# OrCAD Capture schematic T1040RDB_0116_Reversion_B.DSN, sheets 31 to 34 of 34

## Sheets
31 31 Pwr Switch: size B
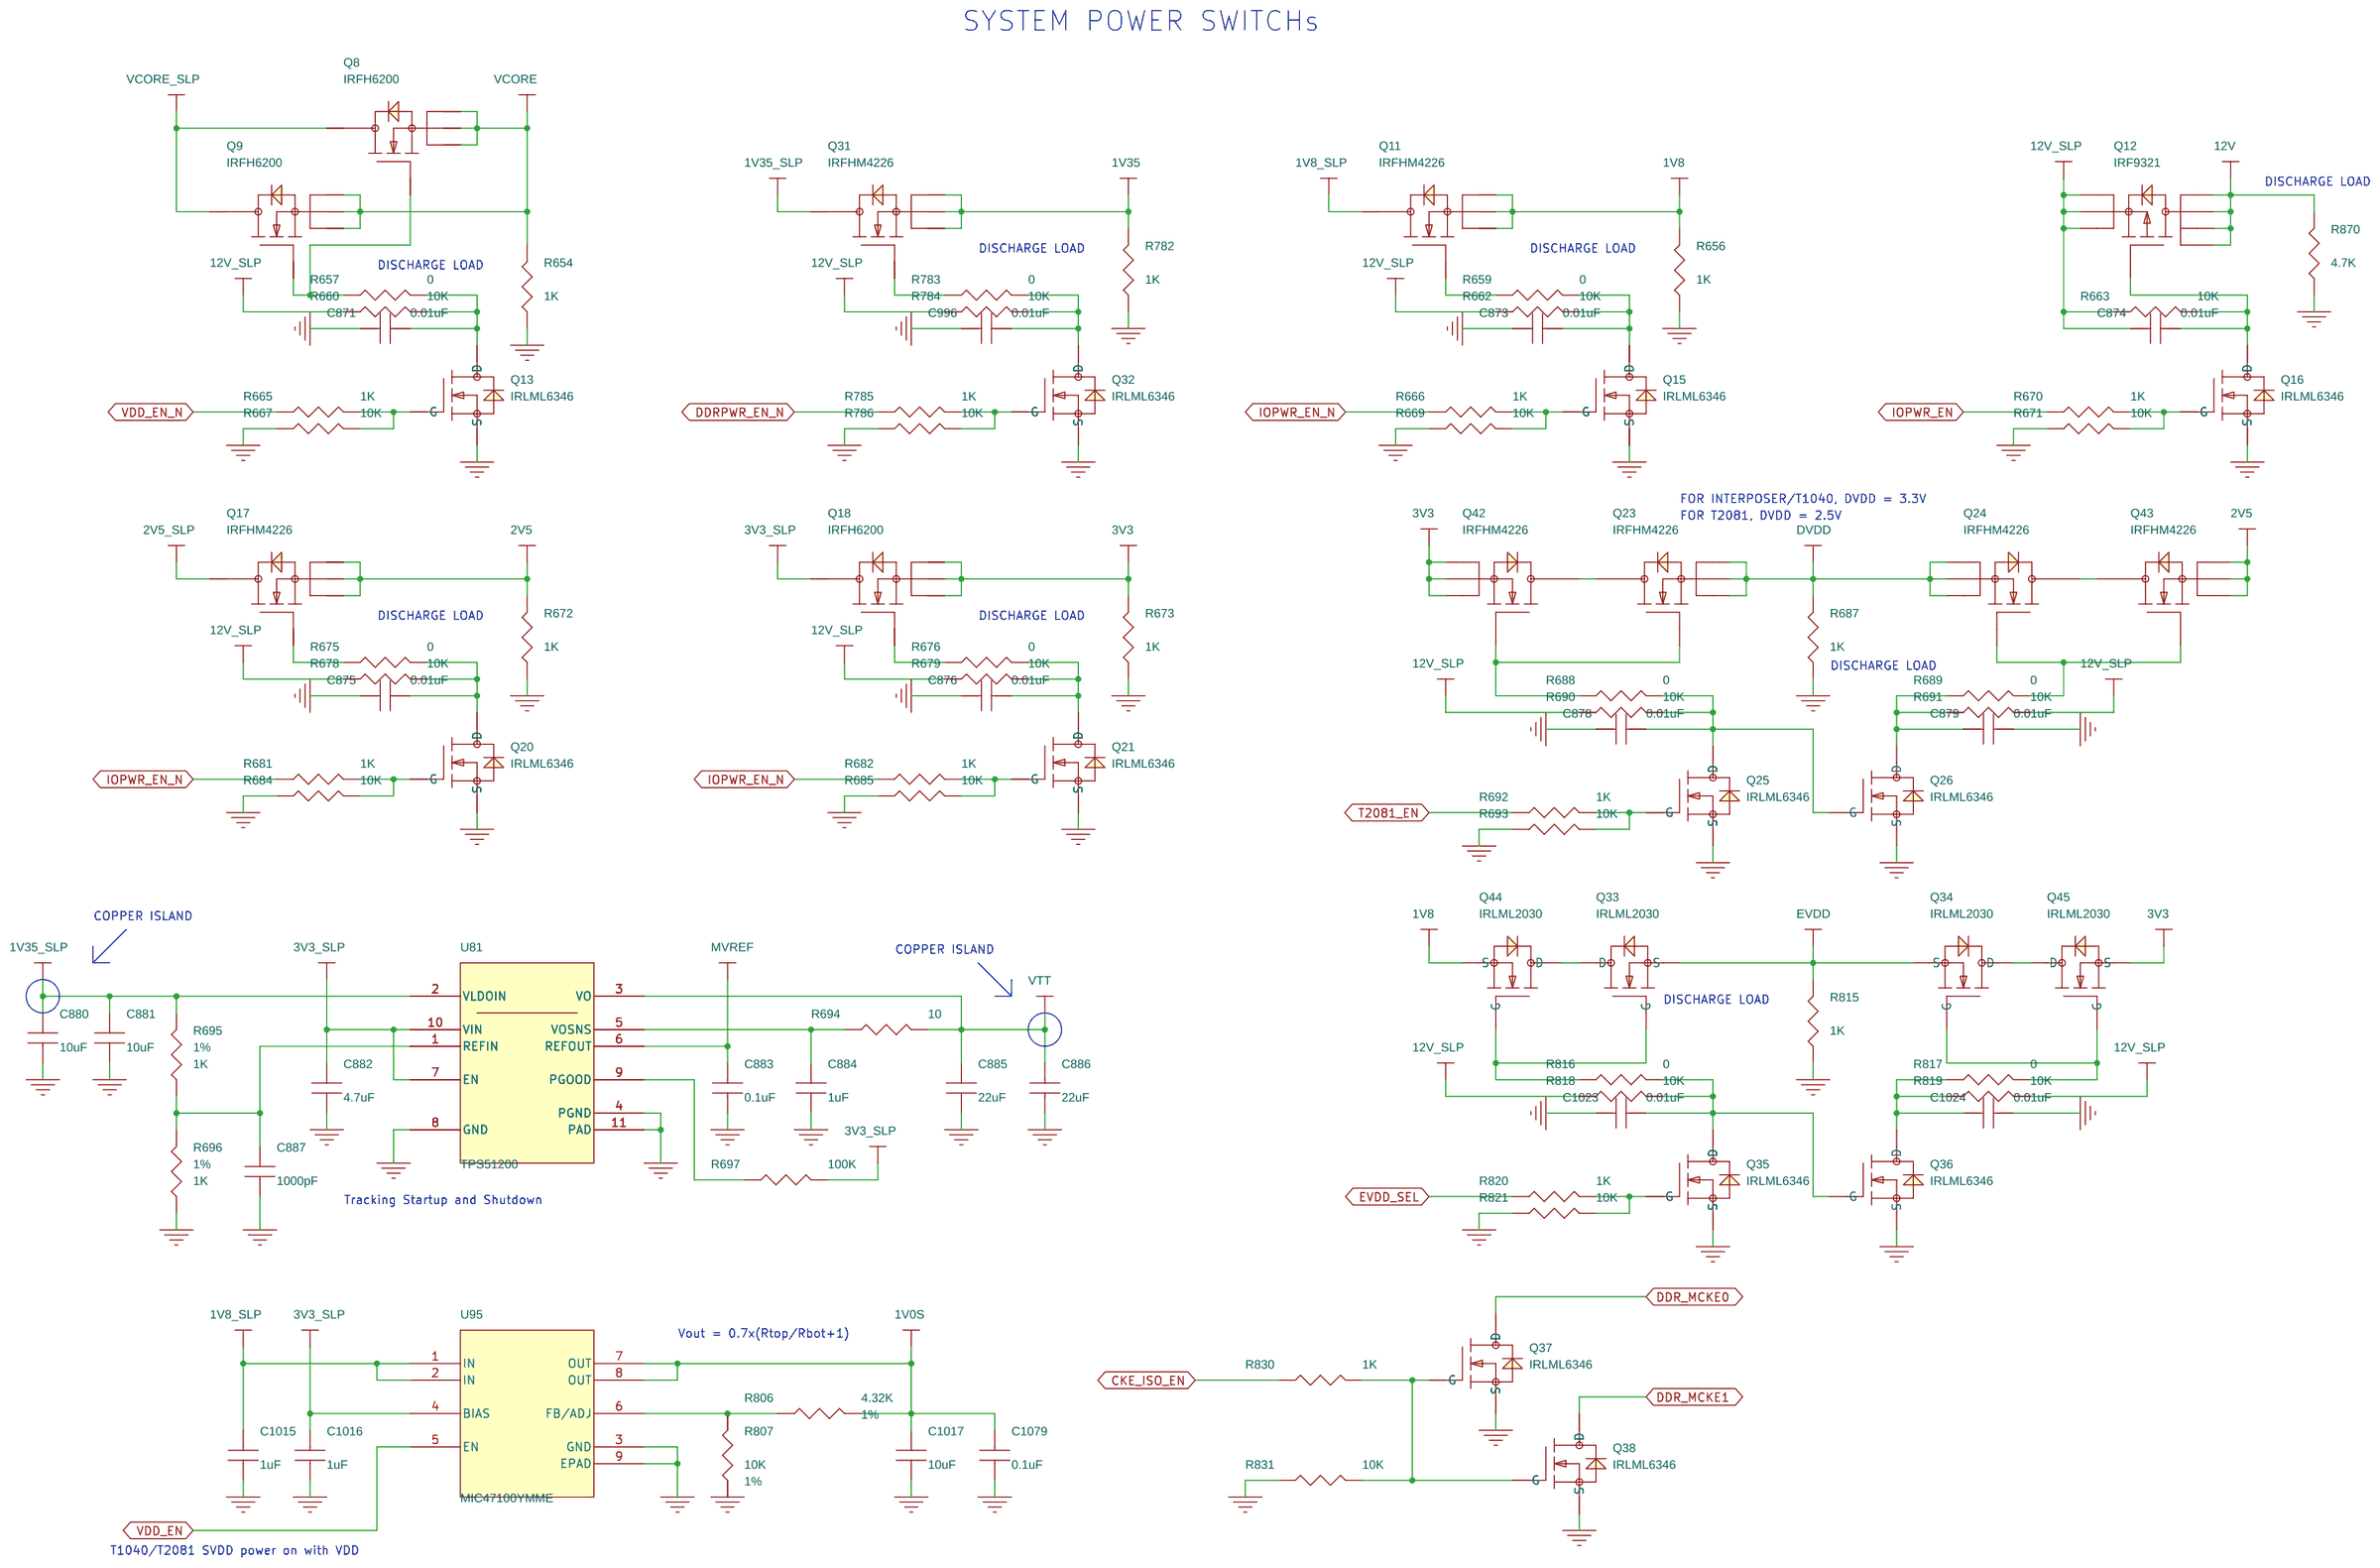
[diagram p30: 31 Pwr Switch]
32 32 Pwr In: size B
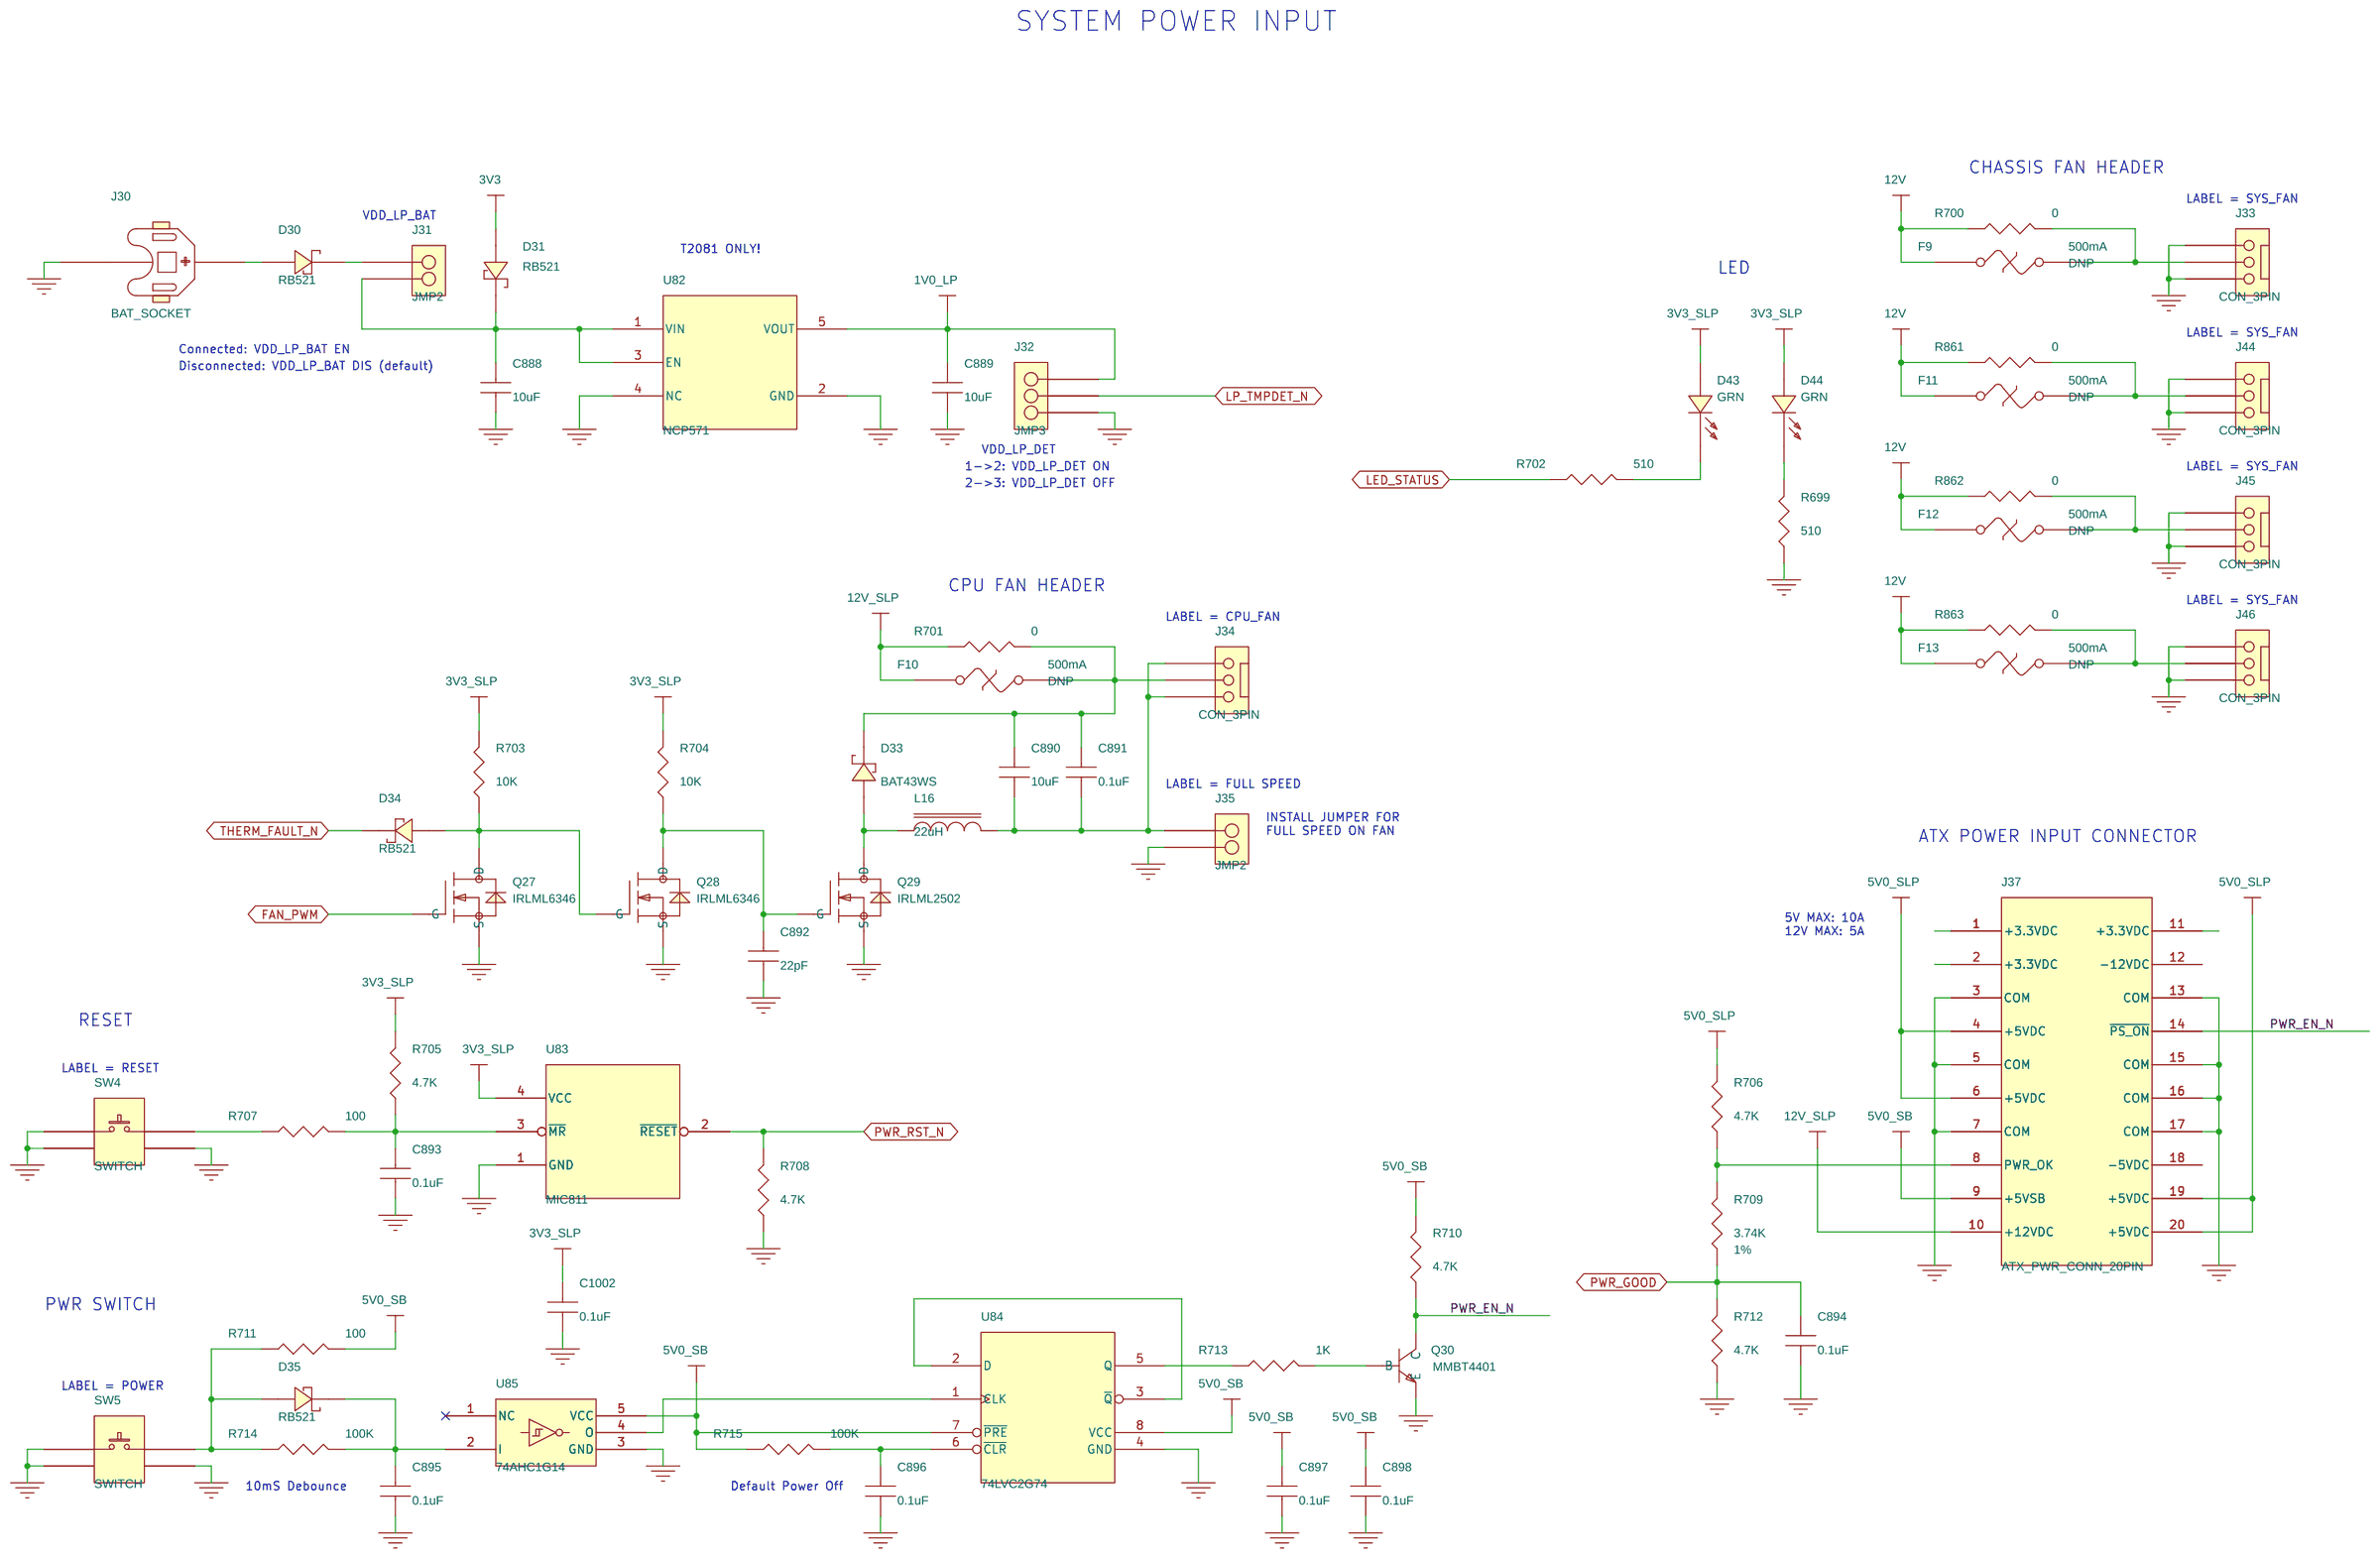
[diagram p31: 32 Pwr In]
33 33 MEC: size B
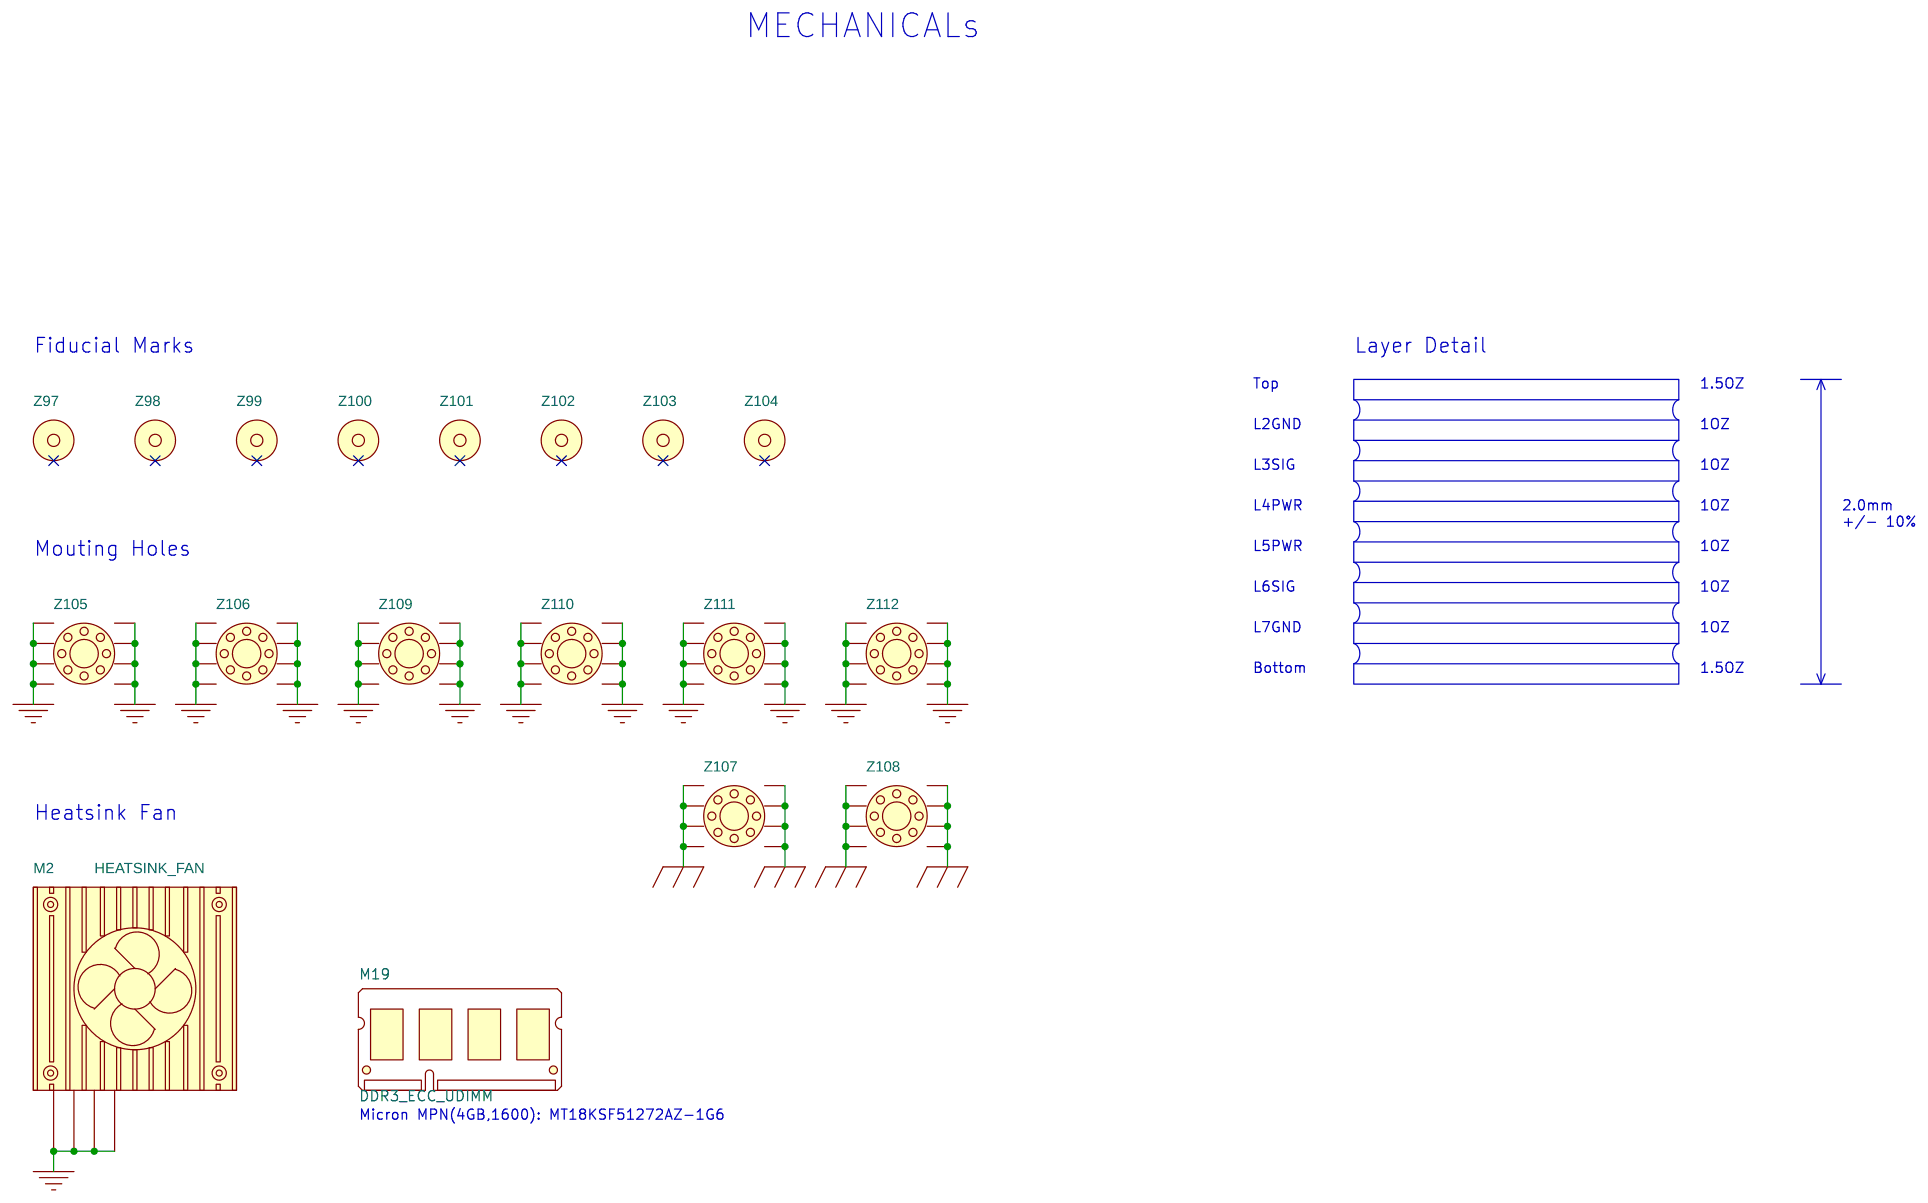
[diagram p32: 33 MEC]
34 34 Change List
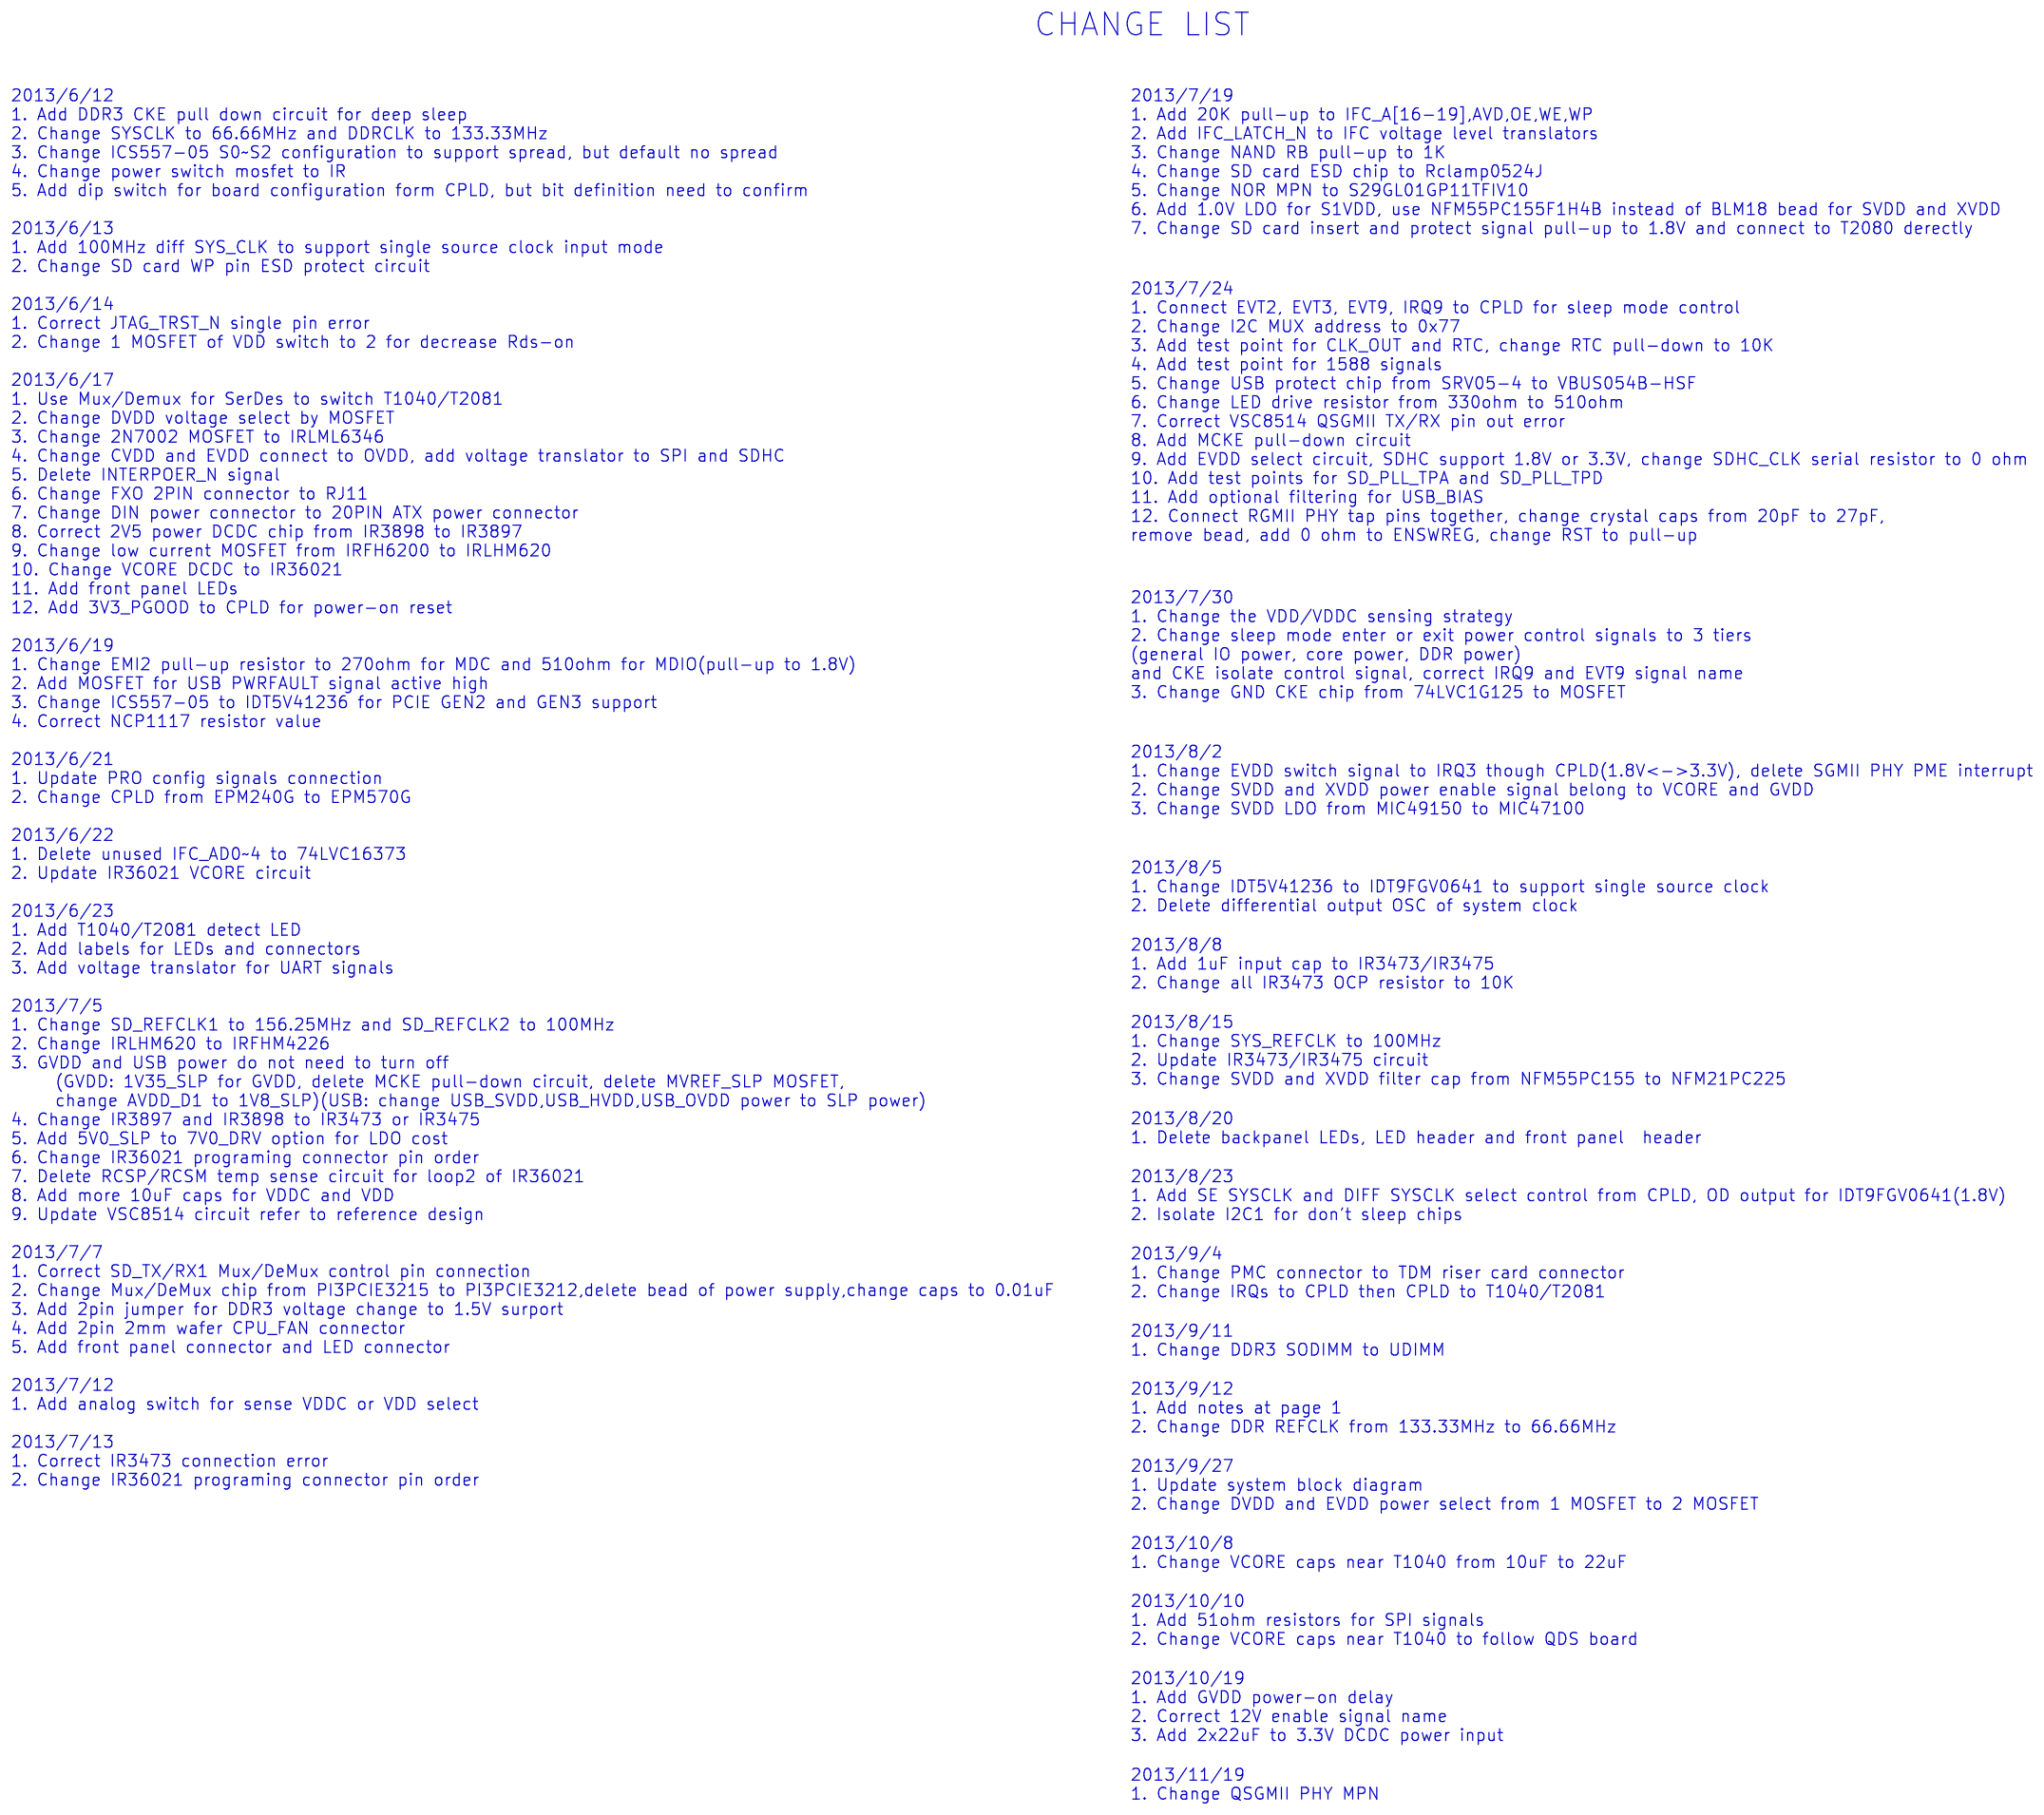
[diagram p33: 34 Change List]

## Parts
sheet 31 Pwr Switch
C871  0.01uF  [0402]
C873  0.01uF  [0402]
C874  0.01uF  [0402]
C875  0.01uF  [0402]
C876  0.01uF  [0402]
C878  0.01uF  [0402]
C879  0.01uF  [0402]
C880  10uF  [0603]
C881  10uF  [0603]
C882  4.7uF  [0603]
C883  0.1uF  [0402]
C884  1uF  [0402]
C885  22uF  [0805]
C886  22uF  [0805]
C887  1000pF  [0402]
C996  0.01uF  [0402]
C1015  1uF  [0402]
C1016  1uF  [0402]
C1017  10uF  [0603]
C1023  0.01uF  [0402]
C1024  0.01uF  [0402]
C1079  0.1uF  [0402]
Q8  IRFH6200  [so_8_fl]
Q9  IRFH6200  [so_8_fl]
Q11  IRFHM4226  [u8_fl]
Q12  IRF9321  [so_8]
Q13  IRLML6346  [sot23]
Q15  IRLML6346  [sot23]
Q16  IRLML6346  [sot23]
Q17  IRFHM4226  [u8_fl]
Q18  IRFH6200  [so_8_fl]
Q20  IRLML6346  [sot23]
Q21  IRLML6346  [sot23]
Q23  IRFHM4226  [u8_fl]
Q24  IRFHM4226  [u8_fl]
Q25  IRLML6346  [sot23]
Q26  IRLML6346  [sot23]
Q31  IRFHM4226  [u8_fl]
Q32  IRLML6346  [sot23]
Q33  IRLML2030  [sot23]
Q34  IRLML2030  [sot23]
Q35  IRLML6346  [sot23]
Q36  IRLML6346  [sot23]
Q37  IRLML6346  [sot23]
Q38  IRLML6346  [sot23]
Q42  IRFHM4226  [u8_fl]
Q43  IRFHM4226  [u8_fl]
Q44  IRLML2030  [sot23]
Q45  IRLML2030  [sot23]
R654  1K  [0402]
R656  1K  [0402]
R657  0  [0402]
R659  0  [0402]
R660  10K  [0402]
R662  10K  [0402]
R663  10K  [0402]
R665  1K  [0402]
R666  1K  [0402]
R667  10K  [0402]
R669  10K  [0402]
R670  1K  [0402]
R671  10K  [0402]
R672  1K  [0402]
R673  1K  [0402]
R675  0  [0402]
R676  0  [0402]
R678  10K  [0402]
R679  10K  [0402]
R681  1K  [0402]
R682  1K  [0402]
R684  10K  [0402]
R685  10K  [0402]
R687  1K  [0402]
R688  0  [0402]
R689  0  [0402]
R690  10K  [0402]
R691  10K  [0402]
R692  1K  [0402]
R693  10K  [0402]
R694  10  [0402]
R695  1K  [0402]
R696  1K  [0402]
R697  100K  [0402]
R782  1K  [0402]
R783  0  [0402]
R784  10K  [0402]
R785  1K  [0402]
R786  10K  [0402]
R806  4.32K  [0402]
R807  10K  [0402]
R815  1K  [0402]
R816  0  [0402]
R817  0  [0402]
R818  10K  [0402]
R819  10K  [0402]
R820  1K  [0402]
R821  10K  [0402]
R830  1K  [0402]
R831  10K  [0402]
R870  4.7K  [0402]
U81  TPS51200  [dfn_p050_d040_b300_10_e240x165]
U95  MIC47100YMME  [msop_8_e170]
sheet 32 Pwr In
C888  10uF  [0603]
C889  10uF  [0603]
C890  10uF  [1206]
C891  0.1uF  [0603]
C892  22pF  [0402]
C893  0.1uF  [0402]
C894  0.1uF  [0402]
C895  0.1uF  [0402]
C896  0.1uF  [0402]
C897  0.1uF  [0402]
C898  0.1uF  [0402]
C1002  0.1uF  [0402]
D30  RB521  [sod523]
D31  RB521  [sod523]
D33  BAT43WS  [sod323]
D34  RB521  [sod523]
D35  RB521  [sod523]
D43  GRN  [led_pm_1s]
D44  GRN  [led_pm_1s]
F9  500mA  [1206]
F10  500mA  [1206]
F11  500mA  [1206]
F12  500mA  [1206]
F13  500mA  [1206]
J30  BAT_SOCKET  [con_bat_wba3b2]
J31  JMP2  [jmp_p254_t_1x2]
J32  JMP3  [hdr_p254_m_t_1x3]
J33  CON_3PIN  [con_wafer_p254_s_1x3]
J34  CON_3PIN  [con_wafer_p254_s_1x3]
J35  JMP2  [jmp_p254_t_1x2]
J37  ATX_PWR_CONN_20PIN  [con_atx_20pin]
J44  CON_3PIN  [con_wafer_p254_s_1x3]
J45  CON_3PIN  [con_wafer_p254_s_1x3]
J46  CON_3PIN  [con_wafer_p254_s_1x3]
L16  22uH  [ind_45x40]
Q27  IRLML6346  [sot23]
Q28  IRLML6346  [sot23]
Q29  IRLML2502  [sot23]
Q30  MMBT4401  [sot23]
R699  510  [0402]
R700  0  [1206]
R701  0  [1206]
R702  510  [0402]
R703  10K  [0402]
R704  10K  [0402]
R705  4.7K  [0402]
R706  4.7K  [0402]
R707  100  [0402]
R708  4.7K  [0402]
R709  3.74K  [0402]
R710  4.7K  [0402]
R711  100  [0402]
R712  4.7K  [0402]
R713  1K  [0402]
R714  100K  [0402]
R715  100K  [0402]
R861  0  [1206]
R862  0  [1206]
R863  0  [1206]
SW4  SWITCH  [con_sw_60x60_2p2_34]
SW5  SWITCH  [con_sw_60x60_2p2_34]
U82  NCP571  [sot23_5]
U83  MIC811  [sot143]
U84  74LVC2G74  [u8]
U85  74AHC1G14  [sc70_5]
sheet 33 MEC
M2  HEATSINK_FAN  [hs_t1040]
M19  DDR3_ECC_UDIMM  [none]
Z97  FIDUCIAL  [fiducial]
Z98  FIDUCIAL  [fiducial]
Z99  FIDUCIAL  [fiducial]
Z100  FIDUCIAL  [fiducial]
Z101  FIDUCIAL  [fiducial]
Z102  FIDUCIAL  [fiducial]
Z103  FIDUCIAL  [fiducial]
Z104  FIDUCIAL  [fiducial]
Z105  MH_M8  [mh_900c400n_m]
Z106  MH_M8  [mh_900c400n_m]
Z107  MH_M8  [mh_900c400n_m]
Z108  MH_M8  [mh_900c400n_m]
Z109  MH_M8  [mh_900c400n_m]
Z110  MH_M8  [mh_900c400n_m]
Z111  MH_M8  [mh_900c400n_m]
Z112  MH_M8  [mh_900c400n_m]

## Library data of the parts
C871 C873-C876 C878 C879 C890 C891 C996 C1023 C1024 = CAP: VOLTAGE: 25V
C880-C882 C884-C886 C888 C889 C1015-C1017 = CAP: VOLTAGE: 6.3V
C883 C893-C898 C1002 C1079 = CAP: VOLTAGE: 16V
C887 C892 = CAP: VOLTAGE: 50V
Q8 Q9 Q18 = NMOS_SO8FL: MPN: IRFH6200TRPBF; TYPE: MOS; Vendor: IR
Q11 Q17 Q23 Q24 Q31 Q42 Q43 = NMOS_SO8FL: MPN: IRFHM4226TRPBF; TYPE: MOS; Vendor: IR
Q12 = PMOS_SO8: MPN: IRF9321TRPBF; TYPE: MOS; Vendor: IR
Q13 Q15 Q16 Q20 Q21 Q25-Q28 Q32 Q35-Q38 = NMOS: MPN: IRLML6346TRPBF; TYPE: MOS; Vendor: IR
Q33 Q34 Q44 Q45 = NMOS: MPN: IRLML2030TRPBF; TYPE: MOS; Vendor: IR
R654 R656 R657 R659 R660 R662 R663 R665-R667 R669-R673 R675 R676 R678 R679 R681 R682 R684 R685 R687-R694 R697 R699-R708 R710-R715 R782-R786 R815-R821 R830 R831 R861-R863 R870 = RES: TOL: 5%
R695 R696 R709 R806 R807 = RES: TOL: 1%
U81 = TPS51200: MPN: TPS51200DRCT; TYPE: IC; Vendor: TI
U95 = MIC47100-MSOP8: MPN: MIC49150YMM; TYPE: IC; Vendor: Micrel
D30 D31 D34 D35 = DIODE_SCHOTTKY: MPN: RB521S30T1G; TYPE: DIODE; Vendor: ON Semi
D33 = DIODE_SCHOTTKY: MPN: BAT43WS-7-F; TYPE: DIODE; Vendor: DIODES
D43 D44 = LED: MPN: L-96A8YVP/1GD/TG-0L; Vendor: Kingbrignt
F9-F13 = PTC: BOM_IGNORE: DNP; MPN: 1206L050; Vendor: Littelfuse
J30 = BAT_SOCKET: MPN: WBA3B2 U; TYPE: CON; Vendor: WIN WIN PRECISION INDUSTRIAL
J31 J35 = CONN_1X2: MPN: TSW-102-07-F-S; TYPE: HDR; Vendor: Samtec
J32 = CONN_1X3: MPN: TSW-103-07-F-S; TYPE: HDR; Vendor: Samtec
J33 J34 J44-J46 = CONN_3PIN: MPN: WRFB-DS03T2NNAX-X; TYPE: HDR; Vendor: SUPERIOR TECH
J37 = ATX_PWR_CONN_20PIN: MPN: 5566-20A; TYPE: CON; Vendor: MOLEX
L16 = IND_IRON: MPN: MDR43SG220M; TYPE: IND; Vendor: MNC
Q29 = NMOS: MPN: IRLML2502TRPBF; TYPE: MOS; Vendor: IR
Q30 = TRANS_NPN: MPN: MMBT4401T-7-F; TYPE: TRAN; Vendor: DIODES
SW4 SW5 = SWITCH_2P2: MPN: KFC-01-01-01-6*6*7; TYPE: CON; Vendor: UNIT
U82 = NCP571: MPN: NCP571SN10T1G; TYPE: IC; Vendor: ON Semi
U83 = MAX811S: MPN: MIC811SUY; TYPE: IC; Vendor: Micrel
U84 = 74LVC2G74: MPN: SN74LVC2G74DCUR; TYPE: IC; Vendor: TI
U85 = 74LVC1G14: MPN: SN74AHC1G14DCKR; TYPE: IC; Vendor: TI
M2 = HEATSINK_FAN: TYPE: MEC
M19 = DDR_MDL: MPN: MT18KSF51272AZ-1G6; TYPE: MDL; Vendor: Micron
Z97-Z104 = FIDUCIAL
Z105-Z112 = MH_M8

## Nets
1V0_LP: C889.1 J32.1 U82.5(VOUT) ; also on sheet 12
1V0S: C1017.1 C1079.1 R806.2 U95.7(OUT) U95.8(OUT) ; also on sheet 12
1V8: Q11.1 Q11.2 Q11.3 Q44.2(S) R656.2 ; also on sheet 8 12 21
1V8_SLP: C1015.1 Q11.5 U95.1(IN) U95.2(IN) ; also on sheet 12 26 27 30
1V35: Q31.1 Q31.2 Q31.3 R782.2 ; also on sheet 12 13
1V35_SLP: C880.1 C881.1 Q31.5 R695.2 U81.2(VLDOIN) ; also on sheet 3 12 30
2V5: Q17.1 Q17.2 Q17.3 Q43.1 Q43.2 Q43.3 R672.2 ; also on sheet 8 12 16 17 18 19 20
2V5_SLP: Q17.5 ; also on sheet 7 8 12 15 30
3V3: D31.2 Q18.1 Q18.2 Q18.3 Q42.1 Q42.2 Q42.3 Q45.2(S) R673.2 ; also on sheet 3 5 6 7 9 10 12 14 16 17 21 22 23 24 28 29
3V3_SLP: C882.1 C1002.1 C1016.1 D43.2 D44.2 Q18.5 R697.2 R703.2 R704.2 R705.2 U81.7(EN) U81.10(VIN) U83.4(VCC) U95.4(BIAS) ; also on sheet 7 11 12 13 15 26 29 30
5V0_SB: C897.1 C898.1 J37.9(+5VSB) R710.2 R711.2 R715.1 U84.7(~{PRE}) U84.8(VCC) U85.5(VCC)
5V0_SLP: J37.4(+5VDC) J37.6(+5VDC) J37.19(+5VDC) J37.20(+5VDC) R706.2 ; also on sheet 11 29 30
12V: F9.1 F11.1 F12.1 F13.1 Q12.5 Q12.6 Q12.7 Q12.8 R700.1 R861.1 R862.1 R863.1 R870.2 ; also on sheet 10 22 25
12V_SLP: C874.1 F10.1 J37.10(+12VDC) Q12.1 Q12.2 Q12.3 R660.1 R662.1 R663.1 R678.1 R679.1 R690.1 R691.2 R701.1 R784.1 R818.1 R819.2 ; also on sheet 29
-5VDC: J37.18(-5VDC)
-12VDC: J37.12(-12VDC)
DVDD: Q23.1 Q23.2 Q23.3 Q24.1 Q24.2 Q24.3 R687.2 ; also on sheet 7 12 14
GND: C871.1 C873.1 C875.1 C876.1 C878.1 C879.2 C880.2 C881.2 C882.2 C883.2 C884.2 C885.2 C886.2 C887.2 C888.2 C889.2 C892.2 C893.2 C894.2 C895.2 C896.2 C897.2 C898.2 C996.1 C1002.2 C1015.2 C1016.2 C1017.2 C1023.1 C1024.2 C1079.2 J30.2 J32.3 J33.1 J33.3 J35.2 J37.3(COM) J37.5(COM) J37.7(COM) J37.13(COM) J37.15(COM) J37.16(COM) J37.17(COM) J44.1 J44.3 J45.1 J45.3 J46.1 J46.3 M2.1 M2.2 M2.3 M2.4 Q13.2(S) Q15.2(S) Q16.2(S) Q20.2(S) Q21.2(S) Q25.2(S) Q26.2(S) Q27.2(S) Q28.2(S) Q29.2(S) Q30.2(E) Q32.2(S) Q35.2(S) Q36.2(S) Q37.2(S) Q38.2(S) R654.1 R656.1 R667.1 R669.1 R671.1 R672.1 R673.1 R684.1 R685.1 R687.1 R693.1 R696.1 R699.1 R708.1 R712.1 R782.1 R786.1 R807.1 R815.1 R821.1 R831.1 R870.1 SW4.1 SW4.3 SW4.4 SW5.1 SW5.3 SW5.4 U81.4(PGND) U81.8(GND) U81.11(PAD) U82.2(GND) U82.4(NC) U83.1(GND) U84.4(GND) U85.3(GND) U95.3(GND) U95.9(EPAD) Z105.1 Z105.2 Z105.3 Z105.4 Z105.5 Z105.6 Z105.7 Z105.8 Z106.1 Z106.2 Z106.3 Z106.4 Z106.5 Z106.6 Z106.7 Z106.8 Z109.1 Z109.2 Z109.3 Z109.4 Z109.5 Z109.6 Z109.7 Z109.8 Z110.1 Z110.2 Z110.3 Z110.4 Z110.5 Z110.6 Z110.7 Z110.8 Z111.1 Z111.2 Z111.3 Z111.4 Z111.5 Z111.6 Z111.7 Z111.8 Z112.1 Z112.2 Z112.3 Z112.4 Z112.5 Z112.6 Z112.7 Z112.8 ; also on sheet 3 4 5 6 7 8 9 10 11 12 13 14 15 16 17 18 19 20 21 22 23 24 25 26 27 28 29 30
VDD_EN: U95.5(EN) ; also on sheet 26
VDD_EN_N: R665.1 ; also on sheet 26
CKE_ISO_EN: R830.1 ; also on sheet 26
DDR_MCKE0: Q37.3(D) ; also on sheet 3
DDR_MCKE1: Q38.3(D) ; also on sheet 3
DDRPWR_EN_N: R785.1 ; also on sheet 26
EARTH: Z107.1 Z107.2 Z107.3 Z107.4 Z107.5 Z107.6 Z107.7 Z107.8 Z108.1 Z108.2 Z108.3 Z108.4 Z108.5 Z108.6 Z108.7 Z108.8 ; also on sheet 11 14 15 16 17 20 21
EVDD: Q33.2(S) Q34.2(S) R815.2 ; also on sheet 6 12
EVDD_SEL: R820.1 ; also on sheet 26
FAN_PWM: Q27.1(G) ; also on sheet 26
IOPWR_EN: R670.1 ; also on sheet 26 30
IOPWR_EN_N: R666.1 R681.1 R682.1 ; also on sheet 26
LED_STATUS: R702.1 ; also on sheet 26
LP_TMPDET_N: J32.2 ; also on sheet 7
MVREF: C883.1 U81.6(REFOUT) ; also on sheet 3
PWR_EN_N: J37.14(~{PS_ON}) Q30.3(C) R710.1
PWR_GOOD: C894.1 R709.1 R712.2 ; also on sheet 26
PWR_RST_N: R708.2 U83.2(~{RESET}) ; also on sheet 26
T2081_EN: R692.1 ; also on sheet 9 26
THERM_FAULT_N: D34.1 ; also on sheet 14 26
VCORE: Q8.1 Q8.2 Q8.3 Q9.1 Q9.2 Q9.3 R654.2 ; also on sheet 12 29
VCORE_SLP: Q8.5 Q9.5 ; also on sheet 12 29
VTT: C885.1 C886.1 R694.2 U81.3(VO) ; also on sheet 3
N17399246: C893.1 R705.1 R707.2 U83.3(~{MR})
N17399288: R707.1 SW4.2
N17400346: D35.2 R711.1 R714.1 SW5.2
N17401317: U84.1(CLK) U85.4(O)
N17401544: C895.1 D35.1 R714.2 U85.2(I)
N17403382: C890.2 C891.2 J34.1 J34.3 J35.1 L16.2
N17403388: C890.1 C891.1 D33.1 F10.2 J34.2 R701.2
N17523688: U84.2(D) U84.3(~{Q})
N17523697: R713.1 U84.5(Q)
N17523706: C896.1 R715.2 U84.6(~{CLR})
N17523733: D33.2 L16.1 Q29.3(D)
N17524661: C892.1 Q28.3(D) Q29.1(G) R704.1
N17525004: D34.2 Q27.3(D) Q28.1(G) R703.1
N18271716: Q15.1(G) R666.2 R669.2
N18271718: C873.2 Q15.3(D) R659.2 R662.2
N18271794: Q11.4 R659.1
N18272048: Q13.1(G) R665.2 R667.2
N18272050: C871.2 Q13.3(D) R657.2 R660.2
N18272126: Q8.4 Q9.4 R657.1
N18272820: C875.2 Q20.3(D) R675.2 R678.2
N18272822: Q20.1(G) R681.2 R684.2
N18272905: Q17.4 R675.1
N18273179: Q21.1(G) R682.2 R685.2
N18273181: C876.2 Q21.3(D) R676.2 R679.2
N18273262: Q18.4 R676.1
N18273767: Q16.1(G) R670.2 R671.2
N18273907: C874.2 Q12.4 Q16.3(D) R663.2
N18275087: C887.1 R695.1 R696.2 U81.1(REFIN)
N18275123: C884.1 R694.1 U81.5(VOSNS)
N18275169: R697.1 U81.9(PGOOD)
N18562864: Q30.1(B) R713.2
N18563122: J37.8(PWR_OK) R706.1 R709.2
N18564716: C878.2 Q25.3(D) Q26.1(G) R688.2 R690.2
N18564718: Q25.1(G) R692.2 R693.2
N18564801: Q23.4 Q42.4 R688.1
N18564847: Q23.5 Q42.5
N18565254: C888.1 D31.1 J31.2 U82.1(VIN) U82.3(EN)
N18565311: D30.1 J31.1
N18565323: D30.2 J30.1
N18566414: C879.1 Q26.3(D) R689.1 R691.1
N18566880: Q24.4 Q43.4 R689.2
N19623883: C996.2 Q32.3(D) R783.2 R784.2
N19623885: Q32.1(G) R785.2 R786.2
N19623968: Q31.4 R783.1
N20366563: R806.1 R807.2 U95.6(FB/ADJ)
N20553507: Q37.1(G) Q38.1(G) R830.2 R831.2
N20559490: Q35.1(G) R820.2 R821.2
N20559492: C1023.2 Q35.3(D) Q36.1(G) R816.2 R818.2
N20559589: Q33.1(G) Q44.1(G) R816.1
N20559634: Q33.3(D) Q44.3(D)
N20559669: C1024.1 Q36.3(D) R817.1 R819.1
N20559724: Q34.1(G) Q45.1(G) R817.2
N22360230: F9.2 J33.2 R700.2
N22360382: F11.2 J44.2 R861.2
N22360534: F12.2 J45.2 R862.2
N22361017: F13.2 J46.2 R863.2
N22361656: D43.1 R702.2
N22361689: D44.1 R699.2
N22440478: Q34.3(D) Q45.3(D)
N22787926: Q24.5 Q43.5

Not connected (* = marked no-connect by the designer): J37 1(+3.3VDC) 2(+3.3VDC) 11(+3.3VDC); U85 1(NC)*; Z97 1*; Z98 1*; Z99 1*; Z100 1*; Z101 1*; Z102 1*; Z103 1*; Z104 1*

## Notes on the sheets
sheet 31
- SYSTEM POWER SWITCHs
- DISCHARGE LOAD
- DISCHARGE LOAD
- DISCHARGE LOAD
- DISCHARGE LOAD
- FOR INTERPOSER/T1040, DVDD = 3.3V
- FOR T2081, DVDD = 2.5V
- DISCHARGE LOAD
- DISCHARGE LOAD
- DISCHARGE LOAD
- COPPER ISLAND
- COPPER ISLAND
- DISCHARGE LOAD
- Tracking Startup and Shutdown
- Vout = 0.7x(Rtop/Rbot+1)
- T1040/T2081 SVDD power on with VDD
sheet 32
- SYSTEM POWER INPUT
- CHASSIS FAN HEADER
- LABEL = SYS_FAN
- VDD_LP_BAT
- T2081 ONLY!
- LED
- LABEL = SYS_FAN
- Connected: VDD_LP_BAT EN
- Disconnected: VDD_LP_BAT DIS (default)
- VDD_LP_DET
- 1->2: VDD_LP_DET ON
- LABEL = SYS_FAN
- 2->3: VDD_LP_DET OFF
- CPU FAN HEADER
- LABEL = SYS_FAN
- LABEL = CPU_FAN
- LABEL = FULL SPEED
- INSTALL JUMPER FOR
  FULL SPEED ON FAN
- ATX POWER INPUT CONNECTOR
- 5V MAX: 10A
  12V MAX: 5A
- RESET
- LABEL = RESET
- PWR SWITCH
- LABEL = POWER
- 10mS Debounce
- Default Power Off
sheet 33
- MECHANICALs
- Fiducial Marks
- Layer Detail
- Top
- 1.5OZ
- L2GND
- 1OZ
- L3SIG
- 1OZ
- L4PWR
- 1OZ
- 2.0mm
  +/- 10%
- Mouting Holes
- L5PWR
- 1OZ
- L6SIG
- 1OZ
- L7GND
- 1OZ
- Bottom
- 1.5OZ
- Heatsink Fan
- Micron MPN(4GB,1600): MT18KSF51272AZ-1G6
sheet 34
- CHANGE LIST
- 2013/6/12
  1. Add DDR3 CKE pull down circuit for deep sleep
  2. Change SYSCLK to 66.66MHz and DDRCLK to 133.33MHz
  3. Change ICS557-05 S0~S2 configuration to support spread, but default no spread
  4. Change power switch mosfet to IR
  5. Add dip switch for board configuration form CPLD, but bit definition need to confirm
  2013/6/13
  1. Add 100MHz diff SYS_CLK to support single source clock input mode
  2. Change SD card WP pin ESD protect circuit
  2013/6/14
  1. Correct JTAG_TRST_N single pin error
  2. Change 1 MOSFET of VDD switch to 2 for decrease Rds-on
  2013/6/17
  1. Use Mux/Demux for SerDes to switch T1040/T2081
  2. Change DVDD voltage select by MOSFET
  3. Change 2N7002 MOSFET to IRLML6346
  4. Change CVDD and EVDD connect to OVDD, add voltage translator to SPI and SDHC
  5. Delete INTERPOER_N signal
  6. Change FXO 2PIN connector to RJ11
  7. Change DIN power connector to 20PIN ATX power connector
  8. Correct 2V5 power DCDC chip from IR3898 to IR3897
  9. Change low current MOSFET from IRFH6200 to IRLHM620
  10. Change VCORE DCDC to IR36021
  11. Add front panel LEDs
  12. Add 3V3_PGOOD to CPLD for power-on reset
  2013/6/19
  1. Change EMI2 pull-up resistor to 270ohm for MDC and 510ohm for MDIO(pull-up to 1.8V)
  2. Add MOSFET for USB PWRFAULT signal active high
  3. Change ICS557-05 to IDT5V41236 for PCIE GEN2 and GEN3 support
  4. Correct NCP1117 resistor value
  2013/6/21
  1. Update PRO config signals connection
  2. Change CPLD from EPM240G to EPM570G
  2013/6/22
  1. Delete unused IFC_AD0~4 to 74LVC16373
  2. Update IR36021 VCORE circuit
  2013/6/23
  1. Add T1040/T2081 detect LED
  2. Add labels for LEDs and connectors
  3. Add voltage translator for UART signals
  2013/7/5
  1. Change SD_REFCLK1 to 156.25MHz and SD_REFCLK2 to 100MHz
  2. Change IRLHM620 to IRFHM4226
  3. GVDD and USB power do not need to turn off
  	(GVDD: 1V35_SLP for GVDD, delete MCKE pull-down circuit, delete MVREF_SLP MOSFET,
  	change AVDD_D1 to 1V8_SLP)(USB: change USB_SVDD,USB_HVDD,USB_OVDD power to SLP power)
  4. Change IR3897 and IR3898 to IR3473 or IR3475
  5. Add 5V0_SLP to 7V0_DRV option for LDO cost
  6. Change IR36021 programing connector pin order
  7. Delete RCSP/RCSM temp sense circuit for loop2 of IR36021
  8. Add more 10uF caps for VDDC and VDD
  9. Update VSC8514 circuit refer to reference design
  2013/7/7
  1. Correct SD_TX/RX1 Mux/DeMux control pin connection
  2. Change Mux/DeMux chip from PI3PCIE3215 to PI3PCIE3212,delete bead of power supply,change caps to 0.01uF
  3. Add 2pin jumper for DDR3 voltage change to 1.5V surport
  4. Add 2pin 2mm wafer CPU_FAN connector
  5. Add front panel connector and LED connector
  2013/7/12
  1. Add analog switch for sense VDDC or VDD select
  2013/7/13
  1. Correct IR3473 connection error
  2. Change IR36021 programing connector pin order
- 2013/7/19
  1. Add 20K pull-up to IFC_A[16-19],AVD,OE,WE,WP
  2. Add IFC_LATCH_N to IFC voltage level translators
  3. Change NAND RB pull-up to 1K
  4. Change SD card ESD chip to Rclamp0524J
  5. Change NOR MPN to S29GL01GP11TFIV10
  6. Add 1.0V LDO for S1VDD, use NFM55PC155F1H4B instead of BLM18 bead for SVDD and XVDD
  7. Change SD card insert and protect signal pull-up to 1.8V and connect to T2080 derectly
- 2013/7/24
  1. Connect EVT2, EVT3, EVT9, IRQ9 to CPLD for sleep mode control
  2. Change I2C MUX address to 0x77
  3. Add test point for CLK_OUT and RTC, change RTC pull-down to 10K
  4. Add test point for 1588 signals
  5. Change USB protect chip from SRV05-4 to VBUS054B-HSF
  6. Change LED drive resistor from 330ohm to 510ohm
  7. Correct VSC8514 QSGMII TX/RX pin out error
  8. Add MCKE pull-down circuit
  9. Add EVDD select circuit, SDHC support 1.8V or 3.3V, change SDHC_CLK serial resistor to 0 ohm
  10. Add test points for SD_PLL_TPA and SD_PLL_TPD
  11. Add optional filtering for USB_BIAS
  12. Connect RGMII PHY tap pins together, change crystal caps from 20pF to 27pF,
  remove bead, add 0 ohm to ENSWREG, change RST to pull-up
- 2013/7/30
  1. Change the VDD/VDDC sensing strategy
  2. Change sleep mode enter or exit power control signals to 3 tiers
  (general IO power, core power, DDR power)
  and CKE isolate control signal, correct IRQ9 and EVT9 signal name
  3. Change GND CKE chip from 74LVC1G125 to MOSFET
- 2013/8/2
  1. Change EVDD switch signal to IRQ3 though CPLD(1.8V<->3.3V), delete SGMII PHY PME interrupt
  2. Change SVDD and XVDD power enable signal belong to VCORE and GVDD
  3. Change SVDD LDO from MIC49150 to MIC47100
- 2013/8/5
  1. Change IDT5V41236 to IDT9FGV0641 to support single source clock
  2. Delete differential output OSC of system clock
- 2013/8/8
  1. Add 1uF input cap to IR3473/IR3475
  2. Change all IR3473 OCP resistor to 10K
- 2013/8/15
  1. Change SYS_REFCLK to 100MHz
  2. Update IR3473/IR3475 circuit
  3. Change SVDD and XVDD filter cap from NFM55PC155 to NFM21PC225
- 2013/8/20
  1. Delete backpanel LEDs, LED header and front panel  header
- 2013/8/23
  1. Add SE SYSCLK and DIFF SYSCLK select control from CPLD, OD output for IDT9FGV0641(1.8V)
  2. Isolate I2C1 for don't sleep chips
- 2013/9/4
  1. Change PMC connector to TDM riser card connector
  2. Change IRQs to CPLD then CPLD to T1040/T2081
- 2013/9/11
  1. Change DDR3 SODIMM to UDIMM
- 2013/9/12
  1. Add notes at page 1
  2. Change DDR REFCLK from 133.33MHz to 66.66MHz
- 2013/9/27
  1. Update system block diagram
  2. Change DVDD and EVDD power select from 1 MOSFET to 2 MOSFET
- 2013/10/8
  1. Change VCORE caps near T1040 from 10uF to 22uF
- 2013/10/10
  1. Add 51ohm resistors for SPI signals
  2. Change VCORE caps near T1040 to follow QDS board
- 2013/10/19
  1. Add GVDD power-on delay
  2. Correct 12V enable signal name
  3. Add 2x22uF to 3.3V DCDC power input
- 2013/11/19
  1. Change QSGMII PHY MPN
